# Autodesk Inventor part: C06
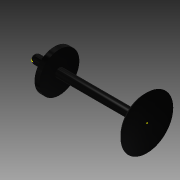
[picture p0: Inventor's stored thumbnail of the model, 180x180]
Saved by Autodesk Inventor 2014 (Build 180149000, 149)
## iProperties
Created: 2006-02
Part Number: C06
Document SubType Name: Modeling
Designer: 40664
Material: Stainless Steel, 440C
Mass: 49.0738 g
Surface Area: 50.6933 cm^2
Volume: 6.3321 cm^3
Density: 7.75 g/cm^3
Appearance: Glossy - Black
Author: 40664
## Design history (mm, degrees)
sketch "Sketch1"
  geometry: L1 (-77, 3)-(-65, 3); L2 (-65, 3)-(-65, 14); L3 (-2, 8.5)-(-2, 16.5); L4 (-2, 16.5)-(0, 18.5); L5 (0, 18.5)-(0, 0); L6 (-80, 0)-(0, 0); L7 (-96.746, 0)-(16.124, 0) reference; L8 (0, 22.8)-(0, -7.3) reference; L9 (-61.5, 14)-(-61.5, 3); L10 (-61.5, 3)-(-7.5, 3); L11 (-65, 14)-(-61.5, 14); A1 r 3 centre (-77, 0) between (-77, 3) and (-80, 0); A2 r 5.5 centre (-7.5, 8.5) between (-7.5, 3) and (-2, 8.5)
  constraints: 18 end point, 5 point on line, 4 point on circle, 3 perpendicular, 3 tangent, 2 centre point, 1 collinear, 1 parallel
  dimensions: "d2" = 18.5 distance of L4.end L5.end; "d5" = 2 distance between parallel lines of L3 L5; "d6" = 135 deg angle of L5 L4; "d7" = 8 distance of L3.start L3.end; "d11" = 12 distance of L1.start L1.end; "d12" = 3 radius of A1; "d13" = 80 distance of L6.start L5.end; "d14" = 11 distance of L1.end L2.end; "d15" = 3.5 distance of L2.end L9.start
revolve "Revolution1" sketch "Sketch1" stored, may be unused: angle "d0" = 90 deg
workplane "Work Plane1"
workplane "Work Plane2"
sketch "Sketch2"
  geometry: L1 (-77, -3)-(-77, 3); A1 r 3 centre (-77, 0) between (-77, 3) and (-77, -3) reference; 1 further point
  constraints: 2 end point, 1 vertical
body "Solid1"
